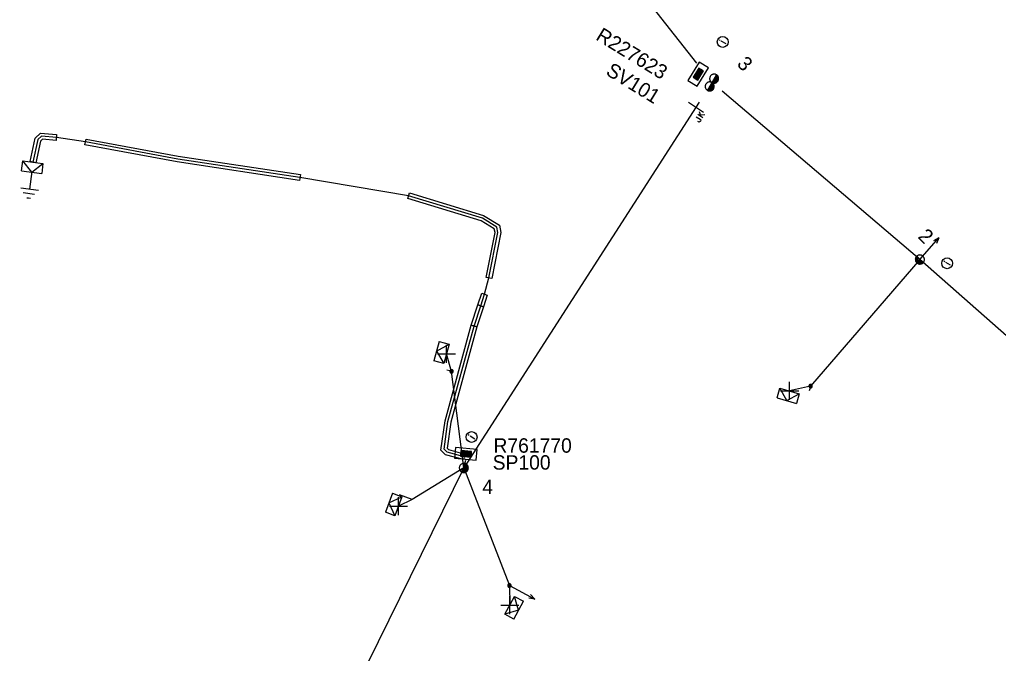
# Model space of a CAD drawing. Extents: x -544780 to -541582, y -1198995 to -1196551.
# Drawn here: x -543887.3 to -543819.5, y -1197388.4 to -1197344.5 of the extents above; entities that cross this region are included whole.
import ezdxf

# ---------------------------------------------------------------- set-up
doc = ezdxf.new("R2010")
doc.units = 0
for name, color, linetype in [('Vrstva 1', 7, 'Continuous'), ('Vrstva 10', 7, 'Continuous'), ('Vrstva 13', 7, 'Continuous'), ('Vrstva 14', 7, 'Continuous'), ('Vrstva 15', 7, 'Continuous'), ('Vrstva 18', 7, 'Continuous'), ('Vrstva 2', 7, 'Continuous'), ('Vrstva 20', 7, 'Continuous'), ('Vrstva 28', 7, 'Continuous'), ('Vrstva 29', 7, 'Continuous'), ('Vrstva 30', 7, 'Continuous'), ('Vrstva 31', 7, 'Continuous'), ('Vrstva 34', 7, 'Continuous'), ('Vrstva 36', 7, 'Continuous'), ('Vrstva 5', 7, 'Continuous'), ('Vrstva 50', 7, 'Continuous'), ('Vrstva 52', 7, 'Continuous'), ('Vrstva 8', 7, 'Continuous'), ('Vrstva 9', 7, 'Continuous')]:
    doc.layers.add(name, color=color, linetype=linetype)

# ---------------------------------------------------------------- blocks, each defined once
blk = doc.blocks.new('NN440')
at = {"layer": 'Vrstva 2'}
for points in [[(0.63, 0), (0.63, 0.06), (0.62, 0.13), (0.6, 0.19), (0.58, 0.25), (0.55, 0.31), (0.51, 0.37), (0.47, 0.42), (0.42, 0.46), (0.37, 0.51), (0.32, 0.54), (0.26, 0.57), (0.2, 0.59), (0.13, 0.61), (0.07, 0.62), (0, 0.63), (-0.06, 0.62), (-0.13, 0.61), (-0.19, 0.59), (-0.26, 0.57), (-0.31, 0.54), (-0.37, 0.51), (-0.42, 0.46), (-0.47, 0.42), (-0.51, 0.37), (-0.54, 0.31), (-0.57, 0.25), (-0.6, 0.19), (-0.62, 0.13), (-0.63, 0.06), (-0.63, 0), (-0.63, -0.07), (-0.62, -0.14), (-0.6, -0.2), (-0.57, -0.26), (-0.54, -0.32), (-0.51, -0.37), (-0.47, -0.43), (-0.42, -0.47), (-0.37, -0.51), (-0.31, -0.55), (-0.26, -0.58), (-0.19, -0.6), (-0.13, -0.62), (-0.06, -0.63), (0, -0.63), (0.07, -0.63), (0.13, -0.62), (0.2, -0.6), (0.26, -0.58), (0.32, -0.55), (0.37, -0.51), (0.42, -0.47), (0.47, -0.43), (0.51, -0.37), (0.55, -0.32), (0.58, -0.26), (0.6, -0.2), (0.62, -0.14), (0.63, -0.07), (0.63, 0)], [(-0.63, 0), (0.63, 0)], [(-0.6, -0.18), (0.57, -0.18)], [(-0.51, -0.32), (0.5, -0.32)], [(-0.37, -0.47), (0.35, -0.47)]]:
    blk.add_lwpolyline(points, dxfattribs=at)
blk = doc.blocks.new('NN450')
at = {"layer": 'Vrstva 2'}
for points in [[(0, 0), (0, 0.07), (-0.01, 0.13), (-0.03, 0.19), (-0.05, 0.25), (-0.08, 0.31), (-0.12, 0.37), (-0.16, 0.42), (-0.21, 0.46), (-0.26, 0.51), (-0.31, 0.54), (-0.37, 0.57), (-0.43, 0.59), (-0.5, 0.61), (-0.56, 0.62), (-0.63, 0.62), (-0.69, 0.62), (-0.75, 0.61), (-0.82, 0.59), (-0.88, 0.57), (-0.94, 0.54), (-0.99, 0.51), (-1.04, 0.46), (-1.09, 0.42), (-1.13, 0.37), (-1.17, 0.31), (-1.2, 0.25), (-1.22, 0.19), (-1.24, 0.13), (-1.25, 0.07), (-1.25, 0), (-1.25, -0.07), (-1.24, -0.13), (-1.22, -0.19), (-1.2, -0.25), (-1.17, -0.31), (-1.13, -0.37), (-1.09, -0.42), (-1.04, -0.46), (-0.99, -0.51), (-0.94, -0.54), (-0.88, -0.57), (-0.82, -0.59), (-0.75, -0.61), (-0.69, -0.62), (-0.62, -0.63), (-0.56, -0.62), (-0.5, -0.61), (-0.43, -0.59), (-0.37, -0.57), (-0.31, -0.54), (-0.26, -0.51), (-0.21, -0.46), (-0.16, -0.42), (-0.12, -0.37), (-0.08, -0.31), (-0.05, -0.25), (-0.03, -0.19), (-0.01, -0.13), (0, -0.07), (0, 0)], [(1.25, 0), (1.25, 0.07), (1.24, 0.13), (1.22, 0.19), (1.2, 0.25), (1.17, 0.31), (1.13, 0.37), (1.09, 0.42), (1.04, 0.46), (0.99, 0.51), (0.94, 0.54), (0.88, 0.57), (0.82, 0.59), (0.75, 0.61), (0.69, 0.62), (0.62, 0.62), (0.56, 0.62), (0.5, 0.61), (0.43, 0.59), (0.37, 0.57), (0.31, 0.54), (0.26, 0.51), (0.21, 0.46), (0.16, 0.42), (0.12, 0.37), (0.08, 0.31), (0.05, 0.25), (0.03, 0.19), (0.01, 0.13), (0, 0.07), (0, 0), (0, -0.07), (0.01, -0.13), (0.03, -0.19), (0.05, -0.25), (0.08, -0.31), (0.12, -0.37), (0.16, -0.42), (0.21, -0.46), (0.26, -0.51), (0.31, -0.54), (0.37, -0.57), (0.43, -0.59), (0.5, -0.61), (0.56, -0.62), (0.63, -0.63), (0.69, -0.62), (0.75, -0.61), (0.82, -0.59), (0.88, -0.57), (0.94, -0.54), (0.99, -0.51), (1.04, -0.46), (1.09, -0.42), (1.13, -0.37), (1.17, -0.31), (1.2, -0.25), (1.22, -0.19), (1.24, -0.13), (1.25, -0.07), (1.25, 0)], [(-1.25, 0), (1.25, 0)], [(-1.23, -0.16), (-0.02, -0.16)], [(-1.16, -0.32), (-0.09, -0.32)], [(-1.03, -0.47), (-0.22, -0.47)], [(0.02, -0.16), (1.23, -0.16)], [(0.09, -0.32), (1.16, -0.32)], [(0.22, -0.47), (1.03, -0.47)]]:
    blk.add_lwpolyline(points, dxfattribs=at)
blk = doc.blocks.new('NN560')
at = {"layer": 'Vrstva 2'}
for points in [[(1.999, -0.001), (1.59, 0.141)], [(0, -0.001), (1.999, -0.001)], [(1.999, -0.001), (1.59, -0.134)]]:
    blk.add_lwpolyline(points, dxfattribs=at)
blk = doc.blocks.new('NN840')
at = {"layer": 'Vrstva 15'}
for points in [[(0.003, 0.619), (0.003, -0.631)], [(-0.745, -0.71), (-0.745, -0.66)], [(-0.538, -0.385), (-0.538, -0.71)], [(-0.332, -0.385), (-0.332, -0.798)], [(-0.332, -0.641), (-0.125, -0.385)], [(-0.263, -0.557), (-0.091, -0.798)], [(-0.73, -0.764), (-0.745, -0.71)], [(-0.657, -0.798), (-0.73, -0.764)], [(-0.627, -0.798), (-0.657, -0.798)], [(-0.558, -0.764), (-0.627, -0.798)], [(-0.538, -0.71), (-0.558, -0.764)]]:
    blk.add_lwpolyline(points, dxfattribs=at)
blk = doc.blocks.new('NN770')
at = {"layer": 'Vrstva 10'}
for p, q in [((0.002, 0.187), (0.002, 0.263)), ((0.002, -0.276), (0.002, 0.111))]:
    blk.add_line(p, q, dxfattribs=at)
blk.add_circle((0, -0.008), 0.375, dxfattribs=at)
blk = doc.blocks.new('NN800')
at = {"layer": 'Vrstva 1'}
for points in [[(-0.442, 0.442), (0.442, -0.442)], [(-0.442, -0.442), (0.442, 0.442)]]:
    blk.add_lwpolyline(points, dxfattribs=at)
blk = doc.blocks.new('NN620')
at = {"layer": 'Vrstva 8'}
for points in [[(0.752, 0.004), (-0.748, 0.004)], [(-0.748, 0.004), (-0.748, -0.746)], [(0.752, -0.746), (0.752, 0.004)], [(0.368, -0.18), (-0.376, -0.18)], [(-0.376, -0.18), (-0.376, -0.558)], [(-0.376, -0.558), (0.368, -0.558)], [(0.321, -0.227), (-0.329, -0.227)], [(-0.329, -0.227), (-0.329, -0.51)], [(-0.329, -0.51), (0.321, -0.51)], [(0.274, -0.274), (-0.281, -0.274)], [(-0.281, -0.274), (-0.281, -0.463)], [(-0.281, -0.463), (0.274, -0.463)], [(0.227, -0.321), (-0.234, -0.321)], [(-0.234, -0.321), (-0.234, -0.416)], [(-0.234, -0.416), (0.227, -0.416)], [(-0.193, -0.369), (0.185, -0.369)], [(0.227, -0.416), (0.227, -0.321)], [(0.274, -0.463), (0.274, -0.274)], [(0.321, -0.51), (0.321, -0.227)], [(0.368, -0.558), (0.368, -0.18)], [(-0.748, -0.746), (0.752, -0.746)]]:
    blk.add_lwpolyline(points, dxfattribs=at)
blk = doc.blocks.new('NN630')
at = {"layer": 'Vrstva 9'}
for points in [[(-0.003, -0.7), (-0.703, 0)], [(-0.703, -0.7), (-0.703, 0), (0.697, 0), (0.697, -0.7)], [(-0.003, -0.7), (0.697, 0)], [(-0.703, -0.7), (0.697, -0.7)]]:
    blk.add_lwpolyline(points, dxfattribs=at)
blk = doc.blocks.new('NN810')
at = {"layer": 'Vrstva 14'}
for points in [[(0.004, -0.64), (0.004, -1.89)], [(0.629, -1.89), (-0.621, -1.89)], [(0.388, -2.2), (-0.399, -2.2)], [(0.004, -2.515), (-0.124, -2.515)], [(0.137, -2.515), (0.004, -2.515)]]:
    blk.add_lwpolyline(points, dxfattribs=at)
blk = doc.blocks.new('NN500')
at = {"layer": 'Vrstva 2'}
for points in [[(0, -0.24), (0.02, -0.23), (0.05, -0.23), (0.07, -0.22), (0.09, -0.22), (0.12, -0.2), (0.14, -0.19), (0.16, -0.18), (0.17, -0.16), (0.19, -0.14), (0.2, -0.12), (0.21, -0.1), (0.22, -0.07), (0.23, -0.05), (0.23, -0.02), (0.23, 0), (0.23, 0.02), (0.23, 0.05), (0.22, 0.07), (0.21, 0.1), (0.2, 0.12), (0.19, 0.14), (0.17, 0.16), (0.16, 0.17), (0.14, 0.19), (0.12, 0.2), (0.09, 0.21), (0.07, 0.22), (0.05, 0.23), (0.02, 0.23), (0, 0.23), (-0.03, 0.23), (-0.05, 0.23), (-0.07, 0.22), (-0.1, 0.21), (-0.12, 0.2), (-0.14, 0.19), (-0.16, 0.17), (-0.18, 0.16), (-0.19, 0.14), (-0.2, 0.12), (-0.22, 0.1), (-0.22, 0.07), (-0.23, 0.05), (-0.23, 0.02), (-0.24, 0), (-0.23, -0.02), (-0.23, -0.05), (-0.22, -0.07), (-0.22, -0.1), (-0.2, -0.12), (-0.19, -0.14), (-0.18, -0.16), (-0.16, -0.18), (-0.14, -0.19), (-0.12, -0.2), (-0.1, -0.22), (-0.07, -0.22), (-0.05, -0.23), (-0.03, -0.23), (0, -0.24)], [(0, -0.24), (0.02, -0.23), (0.05, -0.23), (0.07, -0.22), (0.09, -0.22), (0.12, -0.2), (0.14, -0.19), (0.16, -0.18), (0.17, -0.16), (0.19, -0.14), (0.2, -0.12), (0.21, -0.1), (0.22, -0.07), (0.23, -0.05), (0.23, -0.02), (0.23, 0), (0.23, 0.02), (0.23, 0.05), (0.22, 0.07), (0.21, 0.1), (0.2, 0.12), (0.19, 0.14), (0.17, 0.16), (0.16, 0.17), (0.14, 0.19), (0.12, 0.2), (0.09, 0.21), (0.07, 0.22), (0.05, 0.23), (0.02, 0.23), (0, 0.23), (-0.03, 0.23), (-0.05, 0.23), (-0.07, 0.22), (-0.1, 0.21), (-0.12, 0.2), (-0.14, 0.19), (-0.16, 0.17), (-0.18, 0.16), (-0.19, 0.14), (-0.2, 0.12), (-0.22, 0.1), (-0.22, 0.07), (-0.23, 0.05), (-0.23, 0.02), (-0.24, 0), (-0.23, -0.02), (-0.23, -0.05), (-0.22, -0.07), (-0.22, -0.1), (-0.2, -0.12), (-0.19, -0.14), (-0.18, -0.16), (-0.16, -0.18), (-0.14, -0.19), (-0.12, -0.2), (-0.1, -0.22), (-0.07, -0.22), (-0.05, -0.23), (-0.03, -0.23), (0, -0.24)], [(0, -0.21), (0.02, -0.2), (0.04, -0.2), (0.06, -0.2), (0.08, -0.19), (0.1, -0.18), (0.12, -0.17), (0.14, -0.15), (0.15, -0.14), (0.16, -0.12), (0.18, -0.1), (0.19, -0.08), (0.19, -0.06), (0.2, -0.04), (0.2, -0.02), (0.2, 0), (0.2, 0.02), (0.2, 0.04), (0.19, 0.06), (0.19, 0.08), (0.18, 0.1), (0.16, 0.12), (0.15, 0.14), (0.14, 0.15), (0.12, 0.17), (0.1, 0.18), (0.08, 0.19), (0.06, 0.19), (0.04, 0.2), (0.02, 0.2), (0, 0.2), (-0.02, 0.2), (-0.04, 0.2), (-0.06, 0.19), (-0.08, 0.19), (-0.1, 0.18), (-0.12, 0.17), (-0.14, 0.15), (-0.15, 0.14), (-0.17, 0.12), (-0.18, 0.1), (-0.19, 0.08), (-0.2, 0.06), (-0.2, 0.04), (-0.21, 0.02), (-0.21, 0), (-0.21, -0.02), (-0.2, -0.04), (-0.2, -0.06), (-0.19, -0.08), (-0.18, -0.1), (-0.17, -0.12), (-0.15, -0.14), (-0.14, -0.15), (-0.12, -0.17), (-0.1, -0.18), (-0.08, -0.19), (-0.06, -0.2), (-0.04, -0.2), (-0.02, -0.2), (0, -0.21)], [(0, -0.18), (0.02, -0.18), (0.04, -0.17), (0.05, -0.17), (0.07, -0.16), (0.09, -0.15), (0.1, -0.14), (0.12, -0.13), (0.13, -0.12), (0.14, -0.1), (0.15, -0.09), (0.16, -0.07), (0.17, -0.05), (0.17, -0.04), (0.17, -0.02), (0.17, 0), (0.17, 0.02), (0.17, 0.04), (0.17, 0.05), (0.16, 0.07), (0.15, 0.09), (0.14, 0.1), (0.13, 0.12), (0.12, 0.13), (0.1, 0.14), (0.09, 0.15), (0.07, 0.16), (0.05, 0.17), (0.04, 0.17), (0.02, 0.17), (0, 0.18), (-0.02, 0.17), (-0.04, 0.17), (-0.06, 0.17), (-0.07, 0.16), (-0.09, 0.15), (-0.1, 0.14), (-0.12, 0.13), (-0.13, 0.12), (-0.14, 0.1), (-0.15, 0.09), (-0.16, 0.07), (-0.17, 0.05), (-0.17, 0.04), (-0.18, 0.02), (-0.18, 0), (-0.18, -0.02), (-0.17, -0.04), (-0.17, -0.05), (-0.16, -0.07), (-0.15, -0.09), (-0.14, -0.1), (-0.13, -0.12), (-0.12, -0.13), (-0.1, -0.14), (-0.09, -0.15), (-0.07, -0.16), (-0.06, -0.17), (-0.04, -0.17), (-0.02, -0.18), (0, -0.18)], [(0, -0.15), (0.01, -0.15), (0.03, -0.14), (0.04, -0.14), (0.06, -0.13), (0.07, -0.13), (0.08, -0.12), (0.1, -0.11), (0.11, -0.1), (0.12, -0.09), (0.13, -0.07), (0.13, -0.06), (0.14, -0.05), (0.14, -0.03), (0.14, -0.02), (0.14, 0), (0.14, 0.01), (0.14, 0.03), (0.14, 0.04), (0.13, 0.06), (0.13, 0.07), (0.12, 0.09), (0.11, 0.1), (0.1, 0.11), (0.08, 0.12), (0.07, 0.13), (0.06, 0.13), (0.04, 0.14), (0.03, 0.14), (0.01, 0.14), (0, 0.15), (-0.02, 0.14), (-0.03, 0.14), (-0.05, 0.14), (-0.06, 0.13), (-0.07, 0.13), (-0.09, 0.12), (-0.1, 0.11), (-0.11, 0.1), (-0.12, 0.09), (-0.13, 0.07), (-0.13, 0.06), (-0.14, 0.04), (-0.14, 0.03), (-0.15, 0.01), (-0.15, 0), (-0.15, -0.02), (-0.14, -0.03), (-0.14, -0.05), (-0.13, -0.06), (-0.13, -0.07), (-0.12, -0.09), (-0.11, -0.1), (-0.1, -0.11), (-0.09, -0.12), (-0.07, -0.13), (-0.06, -0.13), (-0.05, -0.14), (-0.03, -0.14), (-0.02, -0.15), (0, -0.15)], [(0, -0.12), (0.01, -0.12), (0.02, -0.11), (0.03, -0.11), (0.05, -0.11), (0.06, -0.1), (0.07, -0.09), (0.08, -0.09), (0.09, -0.08), (0.09, -0.07), (0.1, -0.06), (0.11, -0.05), (0.11, -0.04), (0.11, -0.02), (0.11, -0.01), (0.12, 0), (0.11, 0.01), (0.11, 0.02), (0.11, 0.04), (0.11, 0.05), (0.1, 0.06), (0.09, 0.07), (0.09, 0.08), (0.08, 0.09), (0.07, 0.09), (0.06, 0.1), (0.05, 0.11), (0.03, 0.11), (0.02, 0.11), (0.01, 0.12), (0, 0.12), (-0.01, 0.12), (-0.03, 0.11), (-0.04, 0.11), (-0.05, 0.11), (-0.06, 0.1), (-0.07, 0.09), (-0.08, 0.09), (-0.09, 0.08), (-0.1, 0.07), (-0.1, 0.06), (-0.11, 0.05), (-0.11, 0.04), (-0.12, 0.02), (-0.12, 0.01), (-0.12, 0), (-0.12, -0.01), (-0.12, -0.02), (-0.11, -0.04), (-0.11, -0.05), (-0.1, -0.06), (-0.1, -0.07), (-0.09, -0.08), (-0.08, -0.09), (-0.07, -0.09), (-0.06, -0.1), (-0.05, -0.11), (-0.04, -0.11), (-0.03, -0.11), (-0.01, -0.12), (0, -0.12)], [(0, -0.09), (0.01, -0.09), (0.02, -0.09), (0.03, -0.08), (0.03, -0.08), (0.04, -0.08), (0.05, -0.07), (0.06, -0.07), (0.06, -0.06), (0.07, -0.05), (0.07, -0.04), (0.08, -0.04), (0.08, -0.03), (0.08, -0.02), (0.09, -0.01), (0.09, 0), (0.09, 0.01), (0.08, 0.02), (0.08, 0.03), (0.08, 0.03), (0.07, 0.04), (0.07, 0.05), (0.06, 0.06), (0.06, 0.06), (0.05, 0.07), (0.04, 0.07), (0.03, 0.08), (0.03, 0.08), (0.02, 0.08), (0.01, 0.09), (0, 0.09), (-0.01, 0.09), (-0.02, 0.08), (-0.03, 0.08), (-0.04, 0.08), (-0.04, 0.07), (-0.05, 0.07), (-0.06, 0.06), (-0.07, 0.06), (-0.07, 0.05), (-0.08, 0.04), (-0.08, 0.03), (-0.08, 0.03), (-0.09, 0.02), (-0.09, 0.01), (-0.09, 0), (-0.09, -0.01), (-0.09, -0.02), (-0.08, -0.03), (-0.08, -0.04), (-0.08, -0.04), (-0.07, -0.05), (-0.07, -0.06), (-0.06, -0.07), (-0.05, -0.07), (-0.04, -0.08), (-0.04, -0.08), (-0.03, -0.08), (-0.02, -0.09), (-0.01, -0.09), (0, -0.09)], [(0, -0.06), (0, -0.06), (0.01, -0.06), (0.02, -0.05), (0.02, -0.05), (0.03, -0.05), (0.03, -0.05), (0.04, -0.04), (0.04, -0.04), (0.05, -0.03), (0.05, -0.03), (0.05, -0.02), (0.05, -0.02), (0.05, -0.01), (0.06, -0.01), (0.06, 0), (0.06, 0.01), (0.05, 0.01), (0.05, 0.02), (0.05, 0.02), (0.05, 0.03), (0.05, 0.03), (0.04, 0.04), (0.04, 0.04), (0.03, 0.05), (0.03, 0.05), (0.02, 0.05), (0.02, 0.05), (0.01, 0.06), (0, 0.06), (0, 0.06), (-0.01, 0.06), (-0.01, 0.06), (-0.02, 0.05), (-0.02, 0.05), (-0.03, 0.05), (-0.03, 0.05), (-0.04, 0.04), (-0.04, 0.04), (-0.05, 0.03), (-0.05, 0.03), (-0.05, 0.02), (-0.06, 0.02), (-0.06, 0.01), (-0.06, 0.01), (-0.06, 0), (-0.06, -0.01), (-0.06, -0.01), (-0.06, -0.02), (-0.05, -0.02), (-0.05, -0.03), (-0.05, -0.03), (-0.04, -0.04), (-0.04, -0.04), (-0.03, -0.05), (-0.03, -0.05), (-0.02, -0.05), (-0.02, -0.05), (-0.01, -0.06), (-0.01, -0.06), (0, -0.06)], [(0, -0.03), (0, -0.03), (0, -0.03), (0.01, -0.03), (0.01, -0.03), (0.01, -0.02), (0.02, -0.02), (0.02, -0.02), (0.02, -0.02), (0.02, -0.02), (0.02, -0.01), (0.02, -0.01), (0.03, -0.01), (0.03, -0.01), (0.03, 0), (0.03, 0), (0.03, 0), (0.03, 0.01), (0.03, 0.01), (0.02, 0.01), (0.02, 0.01), (0.02, 0.02), (0.02, 0.02), (0.02, 0.02), (0.02, 0.02), (0.01, 0.02), (0.01, 0.02), (0.01, 0.03), (0, 0.03), (0, 0.03), (0, 0.03), (0, 0.03), (-0.01, 0.03), (-0.01, 0.03), (-0.01, 0.02), (-0.02, 0.02), (-0.02, 0.02), (-0.02, 0.02), (-0.02, 0.02), (-0.02, 0.02), (-0.03, 0.01), (-0.03, 0.01), (-0.03, 0.01), (-0.03, 0.01), (-0.03, 0), (-0.03, 0), (-0.03, 0), (-0.03, -0.01), (-0.03, -0.01), (-0.03, -0.01), (-0.03, -0.01), (-0.02, -0.02), (-0.02, -0.02), (-0.02, -0.02), (-0.02, -0.02), (-0.02, -0.02), (-0.01, -0.03), (-0.01, -0.03), (-0.01, -0.03), (0, -0.03), (0, -0.03)], [(0.23, 0), (0.7, 0)]]:
    blk.add_lwpolyline(points, dxfattribs=at)
blk = doc.blocks.new('NN510')
at = {"layer": 'Vrstva 2'}
blk.add_lwpolyline([(0.001, 0.002), (0.001, 0.939)], dxfattribs=at)

msp = doc.modelspace()

# ---------------------------------------------------------------- linework, layer by layer
at = {"layer": 'Vrstva 20'}
for points in [[(-543886.605, -1197354.358), (-543886.252, -1197352.726), (-543885.89, -1197352.393), (-543884.773, -1197352.491), (-543884.807, -1197352.889), (-543885.75, -1197352.807), (-543885.888, -1197352.934), (-543886.215, -1197354.442)], [(-543882.734, -1197352.803), (-543876.347, -1197353.983), (-543867.88, -1197355.262), (-543867.94, -1197355.658), (-543876.413, -1197354.377), (-543882.806, -1197353.197)], [(-543860.332, -1197356.529), (-543855.187, -1197358.096), (-543854.092, -1197358.765), (-543853.986, -1197359.28), (-543854.624, -1197362.459), (-543855.016, -1197362.381), (-543854.394, -1197359.28), (-543854.448, -1197359.015), (-543855.353, -1197358.464), (-543860.448, -1197356.911)], [(-543854.94, -1197363.601), (-543855.2, -1197364.411), (-543855.58, -1197364.289), (-543855.32, -1197363.479)], [(-543855.2, -1197364.412), (-543855.66, -1197365.812), (-543856.04, -1197365.688), (-543855.58, -1197364.288)], [(-543855.657, -1197365.803), (-543857.464, -1197372.401), (-543857.718, -1197374.209), (-543857.616, -1197374.311), (-543856.478, -1197374.617), (-543856.582, -1197375.003), (-543857.824, -1197374.669), (-543858.142, -1197374.351), (-543857.856, -1197372.319), (-543856.043, -1197365.697)]]:
    msp.add_lwpolyline(points, close=True, dxfattribs=at)
at = {"layer": 'Vrstva 5'}
msp.add_lwpolyline([(-543856.56, -1197375.58), (-543856.41, -1197375.04), (-543856.448, -1197374.967)], dxfattribs=at)
at = {"layer": 'Vrstva 50'}
for points in [[(-543840.42, -1197347.53), (-543854.759, -1197329.329), (-543856.46, -1197300.73), (-543856.72, -1197267.15), (-543841.08, -1197238.92), (-543837.836, -1197210.101)], [(-543802.901, -1197409.09), (-543799.399, -1197383.654), (-543824.959, -1197361.139), (-543838.655, -1197349.487)], [(-543840.25, -1197350.232), (-543856.56, -1197375.58)], [(-543856.56, -1197375.58), (-543869.91, -1197402.679), (-543886.21, -1197426.379), (-543886.903, -1197427.387)]]:
    msp.add_lwpolyline(points, dxfattribs=at)
at = {"layer": 'Vrstva 52'}
msp.add_lwpolyline([(-543856.53, -1197374.81), (-543857.72, -1197374.49), (-543857.93, -1197374.28), (-543857.66, -1197372.36), (-543855.85, -1197365.75), (-543855.39, -1197364.35), (-543855.13, -1197363.54), (-543854.82, -1197362.42), (-543854.19, -1197359.28), (-543854.27, -1197358.89), (-543855.27, -1197358.28), (-543860.39, -1197356.72), (-543867.91, -1197355.46), (-543876.38, -1197354.18), (-543882.77, -1197353), (-543884.79, -1197352.69), (-543885.82, -1197352.6), (-543886.07, -1197352.83), (-543886.41, -1197354.4)], dxfattribs=at)
at = {"layer": 'Vrstva 8'}
for points in [[(-543824.959, -1197361.139), (-543832.529, -1197369.909), (-543833.982, -1197370.243)], [(-543856.56, -1197375.58), (-543857.408, -1197368.888), (-543857.766, -1197367.673)], [(-543856.56, -1197375.58), (-543860.14, -1197377.775), (-543861.091, -1197378.233)], [(-543856.56, -1197375.58), (-543853.398, -1197383.72), (-543853.378, -1197385.09)]]:
    msp.add_lwpolyline(points, dxfattribs=at)

# ---------------------------------------------------------------- block references
at = {"layer": 'Vrstva 13'}
for name, p, xscale, yscale, rotation in [('NN450', (-543839.368, -1197348.881), 0.5000000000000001, 0.4999999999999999, 60.38898335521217), ('NN440', (-543824.959, -1197361.14), 0.5, 0.5, -44.955755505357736), ('NN500', (-543857.408, -1197368.888), 0.49999999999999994, 0.5000000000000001, 164.75900013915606), ('NN500', (-543832.529, -1197369.909), 0.5000000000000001, 0.5, -106.18199999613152), ('NN440', (-543856.56, -1197375.581), 0.5000000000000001, 0.4999999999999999, 57.24873790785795), ('NN500', (-543853.398, -1197383.72), 0.5, 0.5, -28.309000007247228)]:
    msp.add_blockref(name, p, dxfattribs=dict(at, xscale=xscale, yscale=yscale, rotation=rotation))
for name, p, rotation in [('NN560', (-543824.958, -1197361.138), 48.874313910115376), ('NN510', (-543860.139, -1197377.775), 69.47409996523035), ('NN560', (-543853.398, -1197383.72), -28.308677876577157)]:
    msp.add_blockref(name, p, dxfattribs=dict(at, rotation=rotation))
at = {"layer": 'Vrstva 15', "rotation": -7.12501589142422}
msp.add_blockref('NN810', (-543886.41, -1197354.4), dxfattribs=at)
at = {"layer": 'Vrstva 18', "rotation": 56.879408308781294}
msp.add_blockref('NN840', (-543840.482, -1197350.588), dxfattribs=at)
at = {"layer": 'Vrstva 28'}
for p, rotation in [((-543840.006, -1197348.488), -121.55500004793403), ((-543856.448, -1197374.967), 174.78808056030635)]:
    msp.add_blockref('NN620', p, dxfattribs=dict(at, rotation=rotation))
at = {"layer": 'Vrstva 31'}
for p, rotation in [((-543886.41, -1197354.4), -7.12501589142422), ((-543857.766, -1197367.673), -105.24106661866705), ((-543833.982, -1197370.244), -16.181994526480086), ((-543861.091, -1197378.233), -110.52589998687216), ((-543853.378, -1197385.091), 61.690027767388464)]:
    msp.add_blockref('NN630', p, dxfattribs=dict(at, rotation=rotation))
at = {"layer": 'Vrstva 34'}
for p, rotation in [((-543857.766, -1197367.672), 44.99999995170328), ((-543833.982, -1197370.243), 45), ((-543861.091, -1197378.233), 45), ((-543853.378, -1197385.09), 45)]:
    msp.add_blockref('NN800', p, dxfattribs=dict(at, rotation=rotation))
at = {"layer": 'Vrstva 36'}
for p, rotation in [((-543838.629, -1197346.067), 58.516302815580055), ((-543823.079, -1197361.396), 58.51630274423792), ((-543856.026, -1197373.431), 58.516302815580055)]:
    msp.add_blockref('NN770', p, dxfattribs=dict(at, rotation=rotation))

# ---------------------------------------------------------------- texts
at = {"layer": 'Vrstva 14'}
for s, rotation, p in [('3', 313.113, (-543837.691, -1197347.637)), ('2', 315.044, (-543825.159, -1197359.603)), ('4', 0.019, (-543855.277, -1197377.385))]:
    msp.add_text(s, height=1, rotation=rotation, dxfattribs=at).set_placement(p)
at = {"layer": 'Vrstva 29'}
msp.add_text('R227623', height=1, rotation=328.445, dxfattribs=at).set_placement((-543847.48, -1197345.872))
msp.add_text('R761770', height=1, dxfattribs=at).set_placement((-543854.505, -1197374.524))
at = {"layer": 'Vrstva 30'}
msp.add_text('SV101', height=1, rotation=328.445, dxfattribs=at).set_placement((-543846.787, -1197348.297))
msp.add_text('SP100', height=1, dxfattribs=at).set_placement((-543854.56, -1197375.696))

doc.saveas('drawing.dxf')
